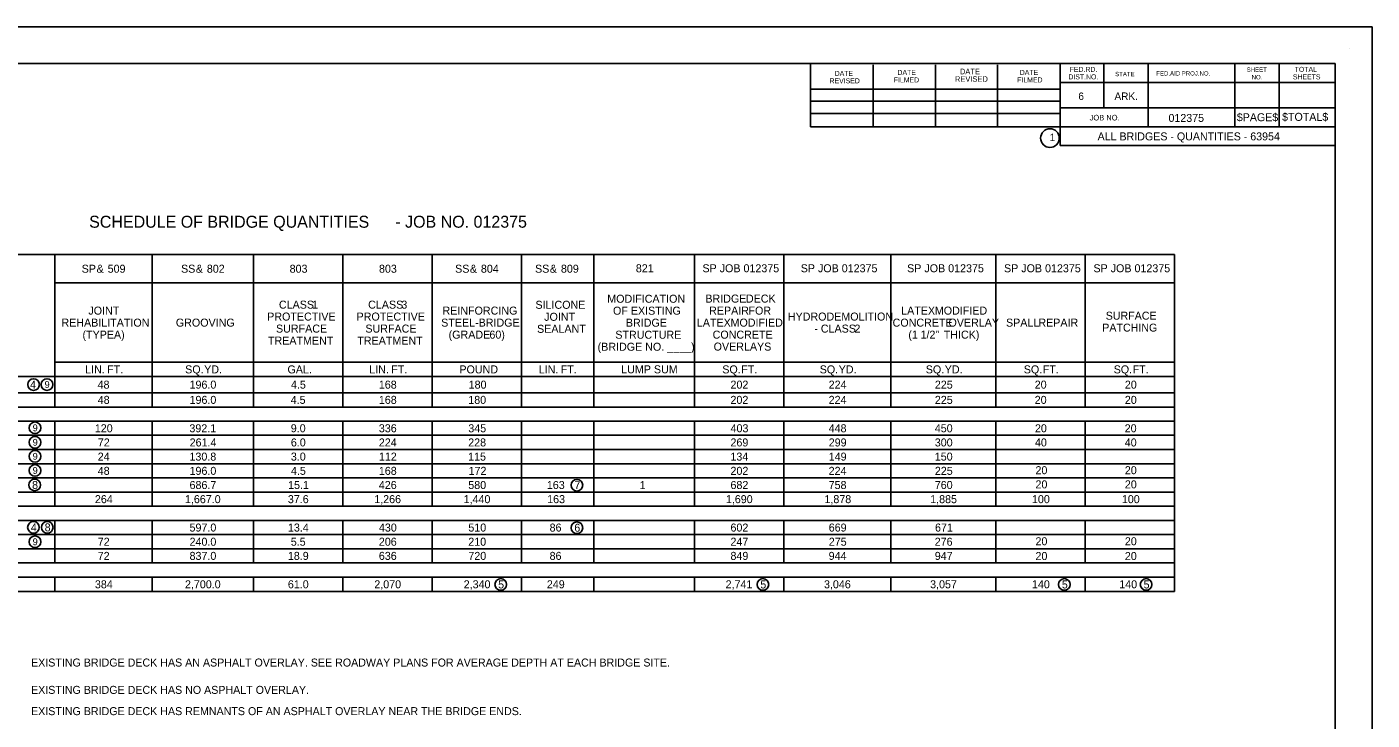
# Model space of a CAD drawing. Extents: x 16 to 1228740, y 11 to 152440.
# Drawn here: x 16.734 to 18.49, y 11.637 to 12.543 of the extents above; entities that cross this region are included whole.
import ezdxf

# ---------------------------------------------------------------- set-up
doc = ezdxf.new("R2010")
doc.units = 0
for name, color, linetype in [('B_Copy In', 7, 'Continuous'), ('B_Rebar', 7, 'Continuous'), ('B_Text', 7, 'Continuous'), ('R_Border', 7, 'Continuous')]:
    doc.layers.add(name, color=color, linetype=linetype)

msp = doc.modelspace()

# ---------------------------------------------------------------- linework, layer by layer
at = {"layer": 'B_Rebar'}
for p, q in [((15.9931, 12.2455), (18.2324, 12.2455)), ((16.7702, 12.0463), (16.7702, 12.2455)), ((16.8971, 12.0463), (16.8971, 12.2455)), ((17.0295, 12.0463), (17.0295, 12.2455)), ((17.1462, 12.0463), (17.1462, 12.2455)), ((17.263, 12.0463), (17.263, 12.2455)), ((17.3797, 12.0463), (17.3797, 12.2455)), ((17.4741, 12.0463), (17.4741, 12.2455)), ((17.6053, 12.0463), (17.6053, 12.2455)), ((17.722, 12.0463), (17.722, 12.2455)), ((17.722, 12.0463), (17.722, 12.2455)), ((17.8619, 12.0463), (17.8619, 12.2455)), ((17.999, 12.0463), (17.999, 12.2455)), ((17.999, 12.0463), (17.999, 12.2455)), ((18.1157, 12.0463), (18.1157, 12.2455)), ((18.2324, 11.8055), (18.2324, 12.2455)), ((16.7702, 12.2084), (18.2324, 12.2084)), ((16.7702, 12.1047), (18.2324, 12.1047)), ((15.9931, 12.0862), (18.2324, 12.0862)), ((17.722, 12.0649), (17.722, 12.0862)), ((17.722, 12.0649), (17.722, 12.0862)), ((17.999, 12.0649), (17.999, 12.0862)), ((17.999, 12.0649), (17.999, 12.0862)), ((16.0616, 12.0649), (18.2324, 12.0649)), ((17.722, 12.0649), (17.8388, 12.0649)), ((17.722, 12.0649), (18.2324, 12.0649)), ((17.999, 12.0649), (18.1027, 12.0649)), ((17.999, 12.0649), (18.2324, 12.0649)), ((15.9931, 12.0463), (18.2324, 12.0463)), ((15.9931, 12.0278), (18.2324, 12.0278)), ((16.7702, 11.9167), (16.7702, 12.0278)), ((16.8971, 11.9167), (16.8971, 12.0278)), ((17.0295, 11.9167), (17.0295, 12.0278)), ((17.1462, 11.9167), (17.1462, 12.0278)), ((17.263, 11.9167), (17.263, 12.0278)), ((17.3797, 11.9167), (17.3797, 12.0278)), ((17.4741, 11.9167), (17.4741, 12.0278)), ((17.6053, 11.9167), (17.6053, 12.0278)), ((17.722, 12.0278), (17.8388, 12.0278)), ((17.722, 12.0093), (17.722, 12.0278)), ((17.722, 12.0093), (17.722, 12.0278)), ((17.722, 11.9167), (17.722, 12.0278)), ((17.722, 11.9167), (17.722, 12.0278)), ((17.8619, 11.9167), (17.8619, 12.0278)), ((17.999, 12.0093), (17.999, 12.0278)), ((17.999, 12.0093), (17.999, 12.0278)), ((17.999, 12.0278), (18.2324, 12.0278)), ((17.999, 11.9167), (17.999, 12.0278)), ((17.999, 11.9167), (17.999, 12.0278)), ((18.1157, 11.9167), (18.1157, 12.0278)), ((16.0616, 12.0093), (18.2324, 12.0093)), ((17.722, 12.0093), (18.2324, 12.0093)), ((16.0616, 11.9908), (18.2324, 11.9908)), ((16.0616, 11.9722), (18.2324, 11.9722)), ((16.0616, 11.9537), (18.2324, 11.9537)), ((16.7702, 11.9537), (16.8971, 11.9537)), ((16.8971, 11.9537), (18.2324, 11.9537)), ((17.8619, 11.9537), (18.2324, 11.9537)), ((16.0616, 11.9352), (18.2324, 11.9352)), ((15.9931, 11.9167), (18.2324, 11.9167)), ((15.9931, 11.8981), (18.2324, 11.8981)), ((16.0616, 11.8981), (18.2324, 11.8981)), ((16.7702, 11.8426), (16.7702, 11.8981)), ((16.8971, 11.8426), (16.8971, 11.8981)), ((17.0295, 11.8426), (17.0295, 11.8981)), ((17.1462, 11.8426), (17.1462, 11.8981)), ((17.263, 11.8426), (17.263, 11.8981)), ((17.3797, 11.8426), (17.3797, 11.8981)), ((17.4741, 11.8426), (17.4741, 11.8981)), ((17.6053, 11.8981), (18.2324, 11.8981)), ((17.6053, 11.8426), (17.6053, 11.8981)), ((17.722, 11.8426), (17.722, 11.8981)), ((17.722, 11.8426), (17.722, 11.8981)), ((17.8619, 11.8426), (17.8619, 11.8981)), ((17.999, 11.8426), (17.999, 11.8981)), ((17.999, 11.8426), (17.999, 11.8981)), ((18.1157, 11.8426), (18.1157, 11.8981)), ((16.0616, 11.8796), (18.2324, 11.8796)), ((17.3797, 11.8611), (17.3797, 11.8796)), ((17.6053, 11.8426), (17.6053, 11.8796)), ((16.0616, 11.8611), (18.2324, 11.8611)), ((17.3797, 11.8611), (17.4964, 11.8611)), ((15.9931, 11.8426), (18.2324, 11.8426)), ((17.6053, 11.8426), (18.2324, 11.8426)), ((15.9931, 11.824), (18.2324, 11.824)), ((16.7702, 11.8055), (16.7702, 11.824)), ((16.8971, 11.8055), (16.8971, 11.824)), ((17.0295, 11.8055), (17.0295, 11.824)), ((17.1462, 11.8055), (17.1462, 11.824)), ((17.263, 11.8055), (17.263, 11.824)), ((17.3797, 11.8055), (17.3797, 11.824)), ((17.4741, 11.8055), (17.4741, 11.824)), ((17.6053, 11.8055), (17.6053, 11.824)), ((17.722, 11.8055), (17.722, 11.824)), ((17.722, 11.8055), (17.722, 11.824)), ((17.8619, 11.8055), (17.8619, 11.824)), ((17.999, 11.8055), (17.999, 11.824)), ((17.999, 11.8055), (17.999, 11.824)), ((18.1157, 11.8055), (18.1157, 11.824)), ((15.9931, 11.8055), (18.2324, 11.8055))]:
    msp.add_line(p, q, dxfattribs=at)
at = {"layer": 'B_Text'}
for centre in [(16.7423, 12.0756), (16.7598, 12.0756), (16.7442, 12.0191), (16.7442, 12.0002), (16.7442, 11.9819), (16.7442, 11.9634), (16.7437, 11.9445), (17.4518, 11.9442), (16.7422, 11.8891), (16.7602, 11.8891), (17.4518, 11.8886), (16.7442, 11.8703), (17.3524, 11.8145), (17.6947, 11.8145), (18.0884, 11.8145), (18.1952, 11.8145)]:
    msp.add_circle(centre, 0.00762, dxfattribs=at)
at = {"layer": 'R_Border'}
for p, q in [((18.4604, 12.514), (18.4604, 12.514)), ((15.7833, 12.4948), (18.4422, 12.4948)), ((17.7567, 12.4124), (17.7567, 12.4948)), ((17.8389, 12.4124), (17.8389, 12.4931)), ((17.9202, 12.4124), (17.9202, 12.4931)), ((18.0009, 12.4124), (18.0009, 12.4931)), ((18.083, 12.4948), (18.083, 12.3881)), ((18.14, 12.4948), (18.14, 12.4369)), ((18.1979, 12.4948), (18.1979, 12.4124)), ((18.311, 12.4948), (18.311, 12.4124)), ((18.3689, 12.4948), (18.3689, 12.4124)), ((18.4422, 10.7576), (18.4422, 12.4948)), ((17.7567, 12.4613), (18.083, 12.4613)), ((18.4422, 12.4703), (18.083, 12.4703)), ((18.4422, 12.4704), (18.4422, 12.4704)), ((17.7567, 12.4458), (18.083, 12.4458)), ((17.7567, 12.4124), (17.7567, 12.4296)), ((17.7567, 12.4296), (18.083, 12.4296)), ((18.4422, 12.4369), (18.083, 12.4369)), ((18.1077, 12.4369), (18.4422, 12.4369)), ((18.4422, 12.4124), (17.7567, 12.4124)), ((18.083, 12.3881), (18.4422, 12.3881)), ((18.083, 12.3881), (18.4422, 12.3881))]:
    msp.add_line(p, q, dxfattribs=at)
msp.add_lwpolyline([(15.6569, 12.5428), (18.4903, 12.5428), (18.4903, 10.7095), (15.6569, 10.7095)], close=True, dxfattribs=at)
msp.add_circle((18.0696, 12.3976), 0.0122, dxfattribs=at)

# ---------------------------------------------------------------- texts
at = {"layer": 'B_Copy In'}
msp.add_text('ALL BRIDGES - QUANTITIES - 63954', height=0.0104, dxfattribs=at).set_placement((18.1318, 12.3946))
at = {"layer": 'B_Text'}
for s, height, p in [('SCHEDULE OF BRIDGE QUANTITIES', 0.015625, (16.8149, 12.2805)), (' - JOB NO. 012375', 0.015625, (17.2089, 12.2805)), ('SP', 0.01045, (16.8051, 12.2217)), (' &', 0.01045, (16.8207, 12.2217)), (' 509', 0.01045, (16.8352, 12.2217)), ('SS', 0.01045, (16.9349, 12.2217)), (' &', 0.01045, (16.9503, 12.2217)), (' 802', 0.01045, (16.9647, 12.2217)), ('803', 0.01045, (17.0767, 12.2217)), ('803', 0.01045, (17.1934, 12.2217)), ('SS', 0.01045, (17.2928, 12.2217)), (' &', 0.01045, (17.3082, 12.2217)), (' 804', 0.01045, (17.3226, 12.2217)), ('SS', 0.01045, (17.3972, 12.2217)), (' &', 0.01045, (17.4126, 12.2217)), (' 809', 0.01045, (17.4271, 12.2217)), ('821', 0.01045, (17.5288, 12.2223)), ('SP JOB 012375', 0.01045, (17.6158, 12.2223)), ('SP JOB 012375', 0.01045, (17.7441, 12.2223)), ('SP JOB 012375', 0.01045, (17.8831, 12.2223)), ('SP JOB 012375', 0.01045, (18.0096, 12.2223)), ('SP JOB 012375', 0.01045, (18.1264, 12.2223)), ('MODIFICATION', 0.01045, (17.4915, 12.1825)), ('BRIDGE', 0.01045, (17.6196, 12.1827)), (' DECK', 0.01045, (17.6687, 12.1827)), ('JOINT', 0.01045, (16.8139, 12.167)), ('CLASS', 0.01045, (17.0627, 12.1748)), (' 1', 0.01045, (17.1022, 12.1748)), ('CLASS', 0.01045, (17.1792, 12.1748)), (' 3', 0.01045, (17.2187, 12.1748)), ('REINFORCING', 0.01045, (17.2763, 12.167)), ('SILICONE', 0.01045, (17.3977, 12.1746)), ('OF EXISTING', 0.01045, (17.499, 12.1669)), ('REPAIR', 0.01045, (17.6245, 12.167)), (' FOR', 0.01045, (17.672, 12.167)), ('LATEX', 0.01045, (17.8753, 12.167)), (' MODIFIED', 0.01045, (17.9154, 12.167)), ('REHABILITATION', 0.01045, (16.7787, 12.1513)), ('GROOVING', 0.01045, (16.9281, 12.1513)), ('PROTECTIVE', 0.01045, (17.0474, 12.1592)), ('PROTECTIVE', 0.01045, (17.1641, 12.1592)), ('STEEL-BRIDGE', 0.01045, (17.2746, 12.1513)), ('JOINT', 0.01045, (17.4091, 12.1589)), ('BRIDGE', 0.01045, (17.5158, 12.1512)), ('LATEX', 0.01045, (17.6085, 12.1513)), (' MODIFIED', 0.01045, (17.6486, 12.1513)), ('HYDRODEMOLITION', 0.01045, (17.7273, 12.1592)), ('CONCRETE', 0.01045, (17.8641, 12.1513)), (' OVERLAY', 0.01045, (17.9332, 12.1513)), ('SPALL', 0.01045, (18.0122, 12.1513)), (' REPAIR', 0.01045, (18.0506, 12.1513)), ('SURFACE ', 0.0104, (18.1424, 12.1604)), ('(TYPE', 0.01045, (16.8062, 12.1356)), (' A)', 0.01045, (16.8434, 12.1356)), ('SURFACE', 0.01045, (17.0589, 12.1435)), ('SURFACE', 0.01045, (17.1756, 12.1435)), ('(GRADE', 0.01045, (17.2843, 12.1356)), (' 60)', 0.01045, (17.3337, 12.1356)), ('SEALANT', 0.01045, (17.3998, 12.1432)), ('STRUCTURE', 0.01045, (17.502, 12.1355)), ('CONCRETE', 0.01045, (17.6291, 12.1356)), ('-', 0.0104, (17.762, 12.1435)), (' CLASS', 0.01045, (17.7665, 12.1435)), (' 2', 0.01045, (17.8104, 12.1435)), ('(1', 0.01045, (17.8847, 12.1356)), (' 1/2"', 0.01045, (17.8967, 12.1356)), (' THICK)', 0.01045, (17.927, 12.1356)), ('PATCHING', 0.0104, (18.1379, 12.1448)), ('TREATMENT', 0.01045, (17.0484, 12.1278)), ('TREATMENT', 0.01045, (17.1651, 12.1278)), ('(BRIDGE NO. ____)', 0.01045, (17.4789, 12.1198)), ('OVERLAYS', 0.01045, (17.6304, 12.12)), ('LIN.', 0.01045, (16.8097, 12.0902)), (' FT.', 0.01045, (16.8345, 12.0902)), ('SQ.', 0.01045, (16.9403, 12.0902)), (' YD.', 0.01045, (16.9612, 12.0902)), ('GAL.', 0.01045, (17.0739, 12.0902)), ('LIN.', 0.01045, (17.1807, 12.0902)), (' FT.', 0.01045, (17.2055, 12.0902)), ('POUND', 0.01045, (17.2984, 12.0902)), ('LIN.', 0.01045, (17.402, 12.0902)), (' FT.', 0.01045, (17.4268, 12.0902)), ('LUMP SUM', 0.01045, (17.5097, 12.0903)), ('SQ.', 0.01045, (17.6417, 12.0902)), (' FT.', 0.01045, (17.6626, 12.0902)), ('SQ.', 0.01045, (17.7689, 12.0902)), (' YD.', 0.01045, (17.7898, 12.0902)), ('SQ.', 0.01045, (17.9074, 12.0902)), (' YD.', 0.01045, (17.9283, 12.0902)), ('SQ.', 0.01045, (18.0354, 12.0902)), (' FT.', 0.01045, (18.0563, 12.0902)), ('SQ.', 0.01045, (18.1528, 12.0902)), (' FT.', 0.01045, (18.1737, 12.0902)), ('4', 0.0104, (16.7378, 12.0704)), ('9', 0.00893, (16.7567, 12.0712)), ('48', 0.01045, (16.8259, 12.0703)), ('196.0', 0.01045, (16.946, 12.0703)), ('4.5', 0.01045, (17.0784, 12.0703)), ('168', 0.01045, (17.1932, 12.0703)), ('180', 0.01045, (17.3105, 12.0703)), ('202', 0.01045, (17.6524, 12.0703)), ('224', 0.01045, (17.7806, 12.0703)), ('225', 0.01045, (17.9193, 12.0703)), ('20', 0.01045, (18.0497, 12.0703)), ('20', 0.01045, (18.1674, 12.0703)), ('48', 0.01045, (16.8261, 12.0504)), ('196.0', 0.01045, (16.946, 12.0504)), ('4.5', 0.01045, (17.0781, 12.0504)), ('168', 0.01045, (17.1932, 12.0504)), ('180', 0.01045, (17.31, 12.0504)), ('202', 0.01045, (17.6524, 12.0504)), ('224', 0.01045, (17.7806, 12.0504)), ('225', 0.01045, (17.9193, 12.0504)), ('20', 0.01045, (18.0497, 12.0504)), ('20', 0.01045, (18.1674, 12.0504)), ('9', 0.00893, (16.7411, 12.0146)), ('120', 0.01045, (16.8223, 12.0133)), ('392.1', 0.01045, (16.9458, 12.0133)), ('9.0', 0.01045, (17.0782, 12.0133)), ('336', 0.01045, (17.1932, 12.0133)), ('345', 0.01045, (17.31, 12.0133)), ('403', 0.01045, (17.6525, 12.0133)), ('448', 0.01045, (17.7806, 12.0133)), ('450', 0.01045, (17.9192, 12.0133)), ('20', 0.01045, (18.05, 12.0133)), ('20', 0.01045, (18.1672, 12.0133)), ('9', 0.00893, (16.7411, 11.9957)), ('72', 0.01045, (16.8262, 11.9948)), ('261.4', 0.01045, (16.9461, 11.9948)), ('6.0', 0.01045, (17.0783, 11.9948)), ('224', 0.01045, (17.1932, 11.9948)), ('228', 0.01045, (17.3099, 11.9948)), ('269', 0.01045, (17.6524, 11.9948)), ('299', 0.01045, (17.7807, 11.9948)), ('300', 0.01045, (17.9192, 11.9948)), ('40', 0.01045, (18.05, 11.9948)), ('40', 0.01045, (18.1673, 11.9948)), ('9', 0.00893, (16.7411, 11.9774)), ('24', 0.01045, (16.8261, 11.9763)), ('130.8', 0.01045, (16.9459, 11.9763)), ('3.0', 0.01045, (17.0783, 11.9763)), ('112', 0.01045, (17.1933, 11.9763)), ('115', 0.01045, (17.3098, 11.9763)), ('134', 0.01045, (17.6523, 11.9763)), ('149', 0.01045, (17.7807, 11.9763)), ('150', 0.01045, (17.9192, 11.9763)), ('9', 0.00893, (16.7411, 11.9589)), ('48', 0.01045, (16.8261, 11.9577)), ('196.0', 0.01045, (16.946, 11.9577)), ('4.5', 0.01045, (17.0784, 11.9577)), ('168', 0.01045, (17.1932, 11.9577)), ('172', 0.01045, (17.3104, 11.9577)), ('202', 0.01045, (17.6524, 11.9577)), ('224', 0.01045, (17.7806, 11.9577)), ('225', 0.01045, (17.9193, 11.9577)), ('20', 0.01045, (18.0507, 11.9585)), ('20', 0.01045, (18.1674, 11.9585)), ('8', 0.0104, (16.7404, 11.9393)), ('686.7', 0.01045, (16.946, 11.9392)), ('15.1', 0.01045, (17.0747, 11.9392)), ('426', 0.01045, (17.1932, 11.9392)), ('580', 0.01045, (17.31, 11.9392)), ('163', 0.01045, (17.4126, 11.9392)), ('7', 0.0104, (17.4485, 11.939)), ('1', 0.0104, (17.5338, 11.9391)), ('682', 0.01045, (17.6524, 11.9392)), ('758', 0.01045, (17.7806, 11.9392)), ('760', 0.01045, (17.9192, 11.9392)), ('20', 0.01045, (18.0507, 11.94)), ('20', 0.01045, (18.1674, 11.94)), ('264', 0.01045, (16.8224, 11.9207)), ('1,667.0', 0.01045, (16.94, 11.9207)), ('37.6', 0.01045, (17.0744, 11.9207)), ('1,266', 0.01045, (17.1872, 11.9207)), ('1,440', 0.01045, (17.3039, 11.9207)), ('163', 0.01045, (17.413, 11.9207)), ('1,690', 0.01045, (17.6464, 11.9207)), ('1,878', 0.01045, (17.7751, 11.9207)), ('1,885', 0.01045, (17.9132, 11.9207)), ('100', 0.01045, (18.0461, 11.9207)), ('100', 0.01045, (18.1635, 11.9207)), ('4', 0.0104, (16.7388, 11.8839)), ('8', 0.0104, (16.7568, 11.8839)), ('597.0', 0.01045, (16.946, 11.8836)), ('13.4', 0.01045, (17.0745, 11.8836)), ('430', 0.01045, (17.1933, 11.8836)), ('510', 0.01045, (17.3101, 11.8836)), ('86', 0.01045, (17.4162, 11.8836)), ('6', 0.0104, (17.4485, 11.8834)), ('602', 0.01045, (17.6524, 11.8836)), ('669', 0.01045, (17.7807, 11.8836)), ('671', 0.01045, (17.9195, 11.8836)), ('72', 0.01045, (16.8261, 11.8651)), ('240.0', 0.01045, (16.946, 11.8651)), ('5.5', 0.01045, (17.0782, 11.8651)), ('206', 0.01045, (17.1932, 11.8651)), ('210', 0.01045, (17.31, 11.8651)), ('247', 0.01045, (17.6524, 11.8651)), ('275', 0.01045, (17.7808, 11.8651)), ('276', 0.01045, (17.9191, 11.8651)), ('20', 0.01045, (18.0507, 11.8657)), ('20', 0.01045, (18.1674, 11.8657)), ('9', 0.00893, (16.7411, 11.8658)), ('72', 0.01045, (16.8261, 11.8466)), ('837.0', 0.01045, (16.946, 11.8466)), ('18.9', 0.01045, (17.0744, 11.8466)), ('636', 0.01045, (17.1932, 11.8466)), ('720', 0.01045, (17.3101, 11.8466)), ('86', 0.01045, (17.4162, 11.8466)), ('849', 0.01045, (17.6524, 11.8466)), ('944', 0.01045, (17.7806, 11.8466)), ('947', 0.01045, (17.9192, 11.8466)), ('20', 0.01045, (18.0507, 11.8464)), ('20', 0.01045, (18.1674, 11.8464)), ('384', 0.01045, (16.8224, 11.8095)), ('2,700.0', 0.01045, (16.94, 11.8095)), ('61.0', 0.01045, (17.0744, 11.8095)), ('2,070', 0.01045, (17.1873, 11.8095)), ('2,340', 0.01045, (17.304, 11.8095)), ('5', 0.0104, (17.349, 11.8093)), ('249', 0.01045, (17.4126, 11.8095)), ('2,741', 0.01045, (17.646, 11.8095)), ('5', 0.0104, (17.6914, 11.8093)), ('3,046', 0.01045, (17.7745, 11.8095)), ('3,057', 0.01045, (17.9131, 11.8095)), ('140', 0.01045, (18.0461, 11.8095)), ('5', 0.0104, (18.0851, 11.8093)), ('140', 0.01045, (18.1601, 11.8095)), ('5', 0.0104, (18.1919, 11.8093)), ('EXISTING BRIDGE DECK HAS AN ASPHALT OVERLAY. SEE ROADWAY PLANS FOR AVERAGE DEPTH AT EACH BRIDGE SITE.', 0.0104167, (16.739, 11.7073)), ('EXISTING BRIDGE DECK HAS NO ASPHALT OVERLAY.', 0.010417, (16.739, 11.6716)), ('EXISTING BRIDGE DECK HAS REMNANTS OF AN ASPHALT OVERLAY NEAR THE BRIDGE ENDS.', 0.010417, (16.739, 11.6438))]:
    msp.add_text(s, height=height, dxfattribs=at).set_placement(p)
at = {"layer": 'R_Border'}
for s, height, p in [('FED.RD.', 0.00652, (18.0954, 12.4841)), ('TOTAL', 0.00652, (18.3892, 12.4841)), ('REVISED', 0.00652, (17.7818, 12.4691)), ('DATE', 0.00652, (17.7885, 12.4788)), ('FILMED', 0.00652, (17.8657, 12.4703)), ('DATE', 0.00652, (17.8705, 12.4801)), ('REVISED', 0.00733, (17.9455, 12.4711)), ('DATE', 0.00733, (17.952, 12.4809)), ('FILMED', 0.00652, (18.0269, 12.4703)), ('DATE', 0.00652, (18.0302, 12.4801)), ('DIST.NO.', 0.00652, (18.0937, 12.4743)), ('STATE', 0.0057, (18.1547, 12.4784)), ('FED.AID PROJ.NO.', 0.0057, (18.2085, 12.4793)), ('SHEET', 0.0057, (18.3265, 12.4841)), ('NO.', 0.0057, (18.333, 12.4743)), ('SHEETS', 0.00652, (18.3869, 12.4743)), ('6', 0.00977, (18.1067, 12.4474)), ('ARK.', 0.00977, (18.1539, 12.4474)), ('JOB NO.', 0.00733, (18.1214, 12.4206)), ('012375', 0.0104, (18.2244, 12.4187)), ('$PAGE$', 0.0104, (18.3136, 12.4196)), ('$TOTAL$', 0.0104, (18.3727, 12.4201)), ('1', 0.00977, (18.0693, 12.3937))]:
    msp.add_text(s, height=height, dxfattribs=at).set_placement(p)

doc.saveas('drawing.dxf')
